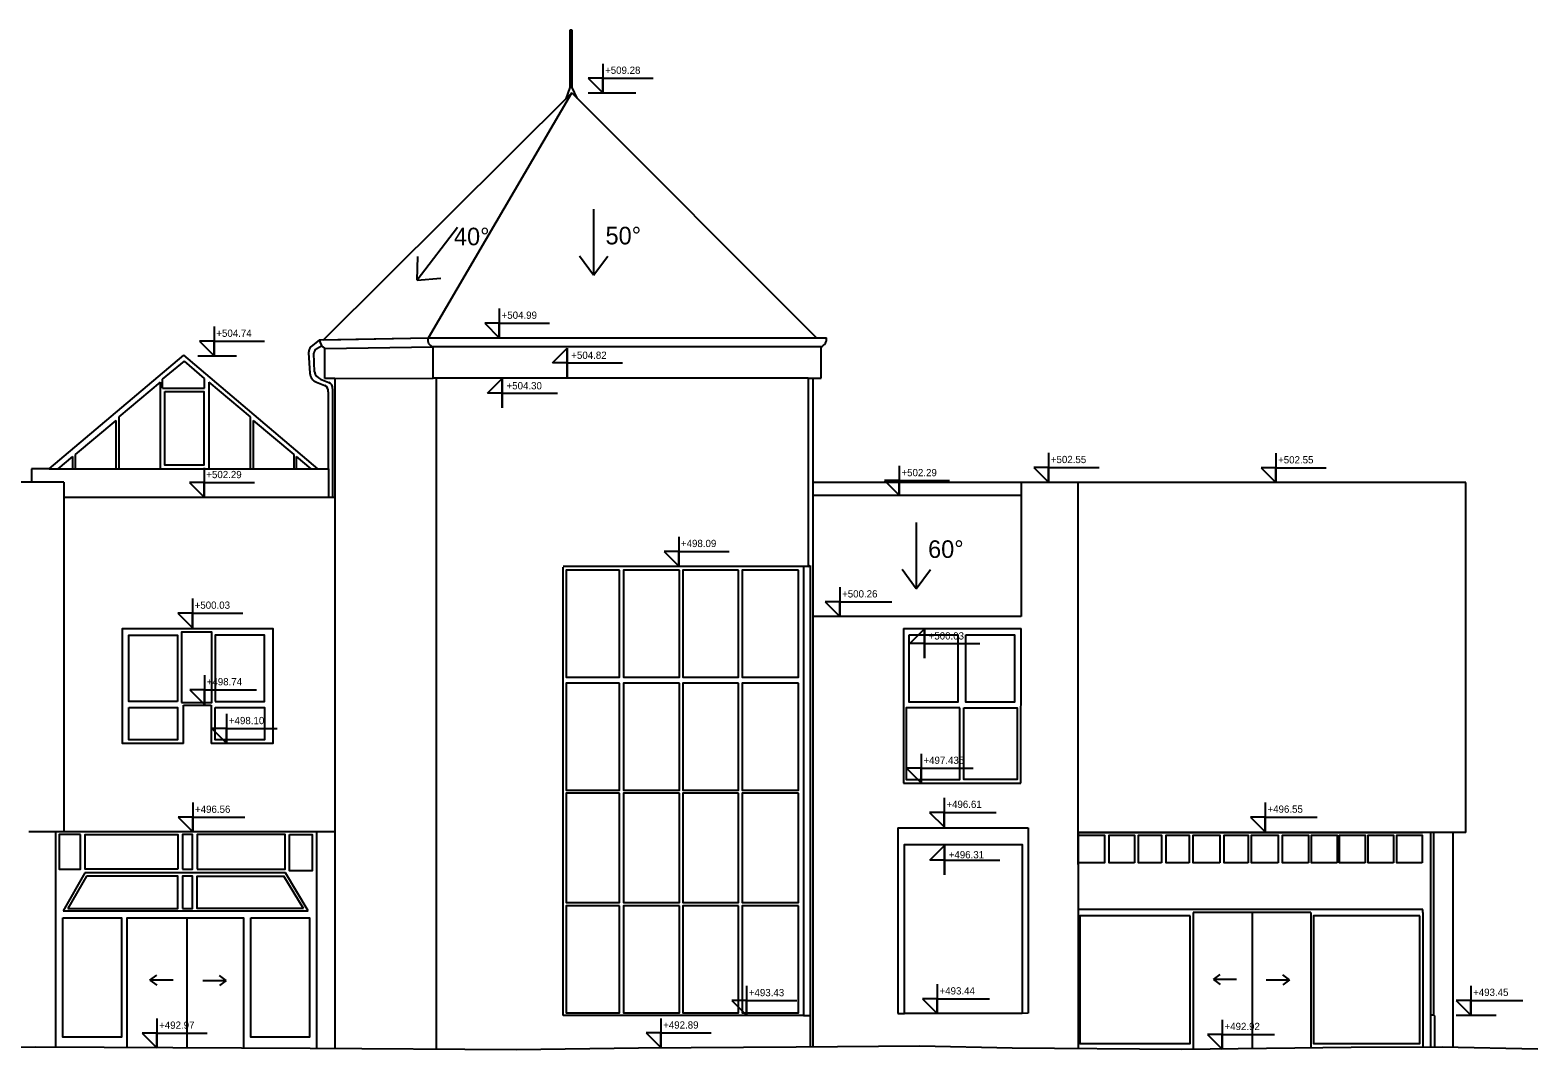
# Model space of a CAD drawing. Extents: x 3.3 to 94, y 492.8 to 514.5.
# Drawn here: x 68.21 to 93.96, y 492.85 to 510.27 of the extents above; entities that cross this region are included whole.
import ezdxf

# ---------------------------------------------------------------- set-up
doc = ezdxf.new("R2010")
doc.units = 0
for name, color, linetype in [('antena', 7, 'Continuous'), ('dvere', 7, 'Continuous'), ('okap', 7, 'Continuous'), ('okna', 7, 'Continuous'), ('strecha_sikma', 7, 'Continuous'), ('svetlik', 7, 'Continuous'), ('teren', 7, 'Continuous'), ('zakl_tenka', 7, 'Continuous'), ('znaceni', 7, 'Continuous')]:
    doc.layers.add(name, color=color, linetype=linetype)

msp = doc.modelspace()

# ---------------------------------------------------------------- linework, layer by layer
at = {"layer": 'antena'}
for p, q in [((77.465, 510.27), (77.425, 510.27)), ((77.425, 510.27), (77.425, 509.29)), ((77.465, 509.29), (77.465, 510.27)), ((77.425, 509.29), (77.355, 509.099)), ((77.55, 509.106), (77.465, 509.29))]:
    msp.add_line(p, q, dxfattribs=at)
at = {"layer": 'dvere'}
for p, q in [((88.07, 495.196), (88.07, 492.859)), ((90.08, 495.196), (88.07, 495.196)), ((89.08, 495.196), (89.08, 492.871)), ((90.08, 495.196), (90.08, 492.882)), ((70.885, 495.109), (70.885, 492.884))]:
    msp.add_line(p, q, dxfattribs=at)
msp.add_lwpolyline([(72.638, 496.531), (73.021, 496.531), (73.021, 495.907), (72.638, 495.907)], close=True, dxfattribs=at)
msp.add_lwpolyline([(69.865, 492.889), (69.865, 495.109), (71.853, 495.109), (71.853, 492.879)], dxfattribs=at)
at = {"layer": 'okap'}
for p, q in [((73.148, 504.977), (73.002, 504.859)), ((73.148, 504.977), (75.009, 505.013)), ((75.009, 505.013), (81.807, 505.012)), ((72.963, 504.759), (72.982, 504.408)), ((73.062, 504.432), (73.053, 504.75)), ((73.101, 504.83), (73.185, 504.876)), ((73.242, 504.834), (75.09, 504.861)), ((81.718, 504.861), (75.09, 504.861)), ((73.096, 504.256), (73.241, 504.199)), ((73.166, 504.31), (73.31, 504.252)), ((73.299, 504.092), (73.299, 502.774)), ((73.369, 504.145), (73.369, 502.293))]:
    msp.add_line(p, q, dxfattribs=at)
for centre, radius, start, end in [((73.335, 504.999), 0.189, 186.7221, 240.5714), ((75.111, 504.97), 0.111, 157.5198, 258.6908), ((81.664, 504.995), 0.144, 291.9434, 6.8704), ((73.12, 504.756), 0.157, 138.9853, 178.7942), ((73.159, 504.741), 0.107, 123.0247, 174.7703), ((73.226, 504.465), 0.167, 191.3772, 249.1497), ((73.171, 504.431), 0.19, 186.8763, 246.9983), ((73.198, 504.106), 0.102, 351.9431, 65.2903), ((73.268, 504.16), 0.102, 351.9431, 65.2903)]:
    msp.add_arc(centre, radius, start, end, dxfattribs=at)
at = {"layer": 'okna'}
for p, q in [((81.413, 501.096), (81.413, 493.438)), ((69.144, 495.874), (68.773, 495.226)), ((69.172, 495.82), (68.853, 495.265)), ((72.569, 495.874), (69.144, 495.874)), ((72.507, 495.874), (72.506, 495.875)), ((72.873, 495.265), (72.539, 495.82)), ((72.958, 495.226), (72.569, 495.874)), ((68.773, 495.226), (72.958, 495.226)), ((91.991, 495.248), (86.103, 495.248))]:
    msp.add_line(p, q, dxfattribs=at)
for points in [[(70.51, 504.1), (71.173, 504.1), (71.173, 502.841), (70.51, 502.841)], [(78.275, 501.045), (77.363, 501.045), (77.363, 499.219), (78.275, 499.219)], [(79.299, 501.045), (78.34, 501.045), (78.34, 499.219), (79.299, 499.219)], [(80.307, 501.045), (79.354, 501.045), (79.354, 499.219), (80.307, 499.219)], [(81.327, 501.045), (80.366, 501.045), (80.366, 499.219), (81.327, 499.219)], [(70.726, 498.805), (69.892, 498.805), (69.892, 499.935), (70.726, 499.935)], [(70.795, 498.787), (71.313, 498.787), (71.313, 499.986), (70.795, 499.986)], [(71.369, 498.805), (72.211, 498.805), (72.211, 499.935), (71.369, 499.935)], [(83.22, 499.939), (84.049, 499.939), (84.049, 498.792), (83.22, 498.792)], [(84.189, 499.939), (85.021, 499.939), (85.021, 498.792), (84.189, 498.792)], [(78.275, 499.115), (77.363, 499.115), (77.363, 497.288), (78.275, 497.288)], [(79.299, 499.115), (78.34, 499.115), (78.34, 497.288), (79.299, 497.288)], [(80.307, 499.115), (79.354, 499.115), (79.354, 497.288), (80.307, 497.288)], [(81.327, 499.115), (80.366, 499.115), (80.366, 497.288), (81.327, 497.288)], [(69.892, 498.7), (70.726, 498.7), (70.726, 498.149), (69.892, 498.149)], [(71.369, 498.7), (72.211, 498.7), (72.211, 498.149), (71.369, 498.149)], [(84.082, 498.696), (83.17, 498.696), (83.17, 497.472), (84.082, 497.472)], [(84.151, 498.696), (85.066, 498.696), (85.066, 497.472), (84.151, 497.472)], [(78.275, 497.234), (77.363, 497.234), (77.363, 495.369), (78.275, 495.369)], [(79.299, 497.234), (78.34, 497.234), (78.34, 495.369), (79.299, 495.369)], [(80.307, 497.234), (79.354, 497.234), (79.354, 495.369), (80.307, 495.369)], [(81.327, 497.234), (80.366, 497.234), (80.366, 495.369), (81.327, 495.369)], [(69.067, 496.531), (68.705, 496.531), (68.705, 495.939), (69.067, 495.939)], [(70.73, 495.939), (69.145, 495.939), (69.145, 496.531), (70.73, 496.531)], [(70.812, 495.941), (70.981, 495.941), (70.981, 496.531), (70.812, 496.531)], [(71.059, 495.941), (72.563, 495.941), (72.563, 496.531), (71.059, 496.531)], [(87.068, 496.044), (86.634, 496.044), (86.634, 496.517), (87.068, 496.517)], [(87.527, 496.044), (87.138, 496.044), (87.138, 496.517), (87.527, 496.517)], [(88.003, 496.044), (87.608, 496.044), (87.608, 496.517), (88.003, 496.517)], [(88.523, 496.044), (88.071, 496.044), (88.071, 496.517), (88.523, 496.517)], [(89.011, 496.044), (88.597, 496.044), (88.597, 496.517), (89.011, 496.517)], [(89.524, 496.044), (89.067, 496.044), (89.067, 496.517), (89.524, 496.517)], [(90.037, 496.044), (89.597, 496.044), (89.597, 496.517), (90.037, 496.517)], [(90.529, 496.044), (90.093, 496.044), (90.093, 496.517), (90.529, 496.517)], [(91.005, 496.044), (90.57, 496.044), (90.57, 496.517), (91.005, 496.517)], [(91.492, 496.044), (91.057, 496.044), (91.057, 496.517), (91.492, 496.517)], [(91.981, 496.044), (91.546, 496.044), (91.546, 496.517), (91.981, 496.517)], [(70.812, 495.265), (70.981, 495.265), (70.981, 495.82), (70.812, 495.82)], [(78.275, 495.31), (77.363, 495.31), (77.363, 493.484), (78.275, 493.484)], [(79.299, 495.31), (78.34, 495.31), (78.34, 493.484), (79.299, 493.484)], [(80.307, 495.31), (79.354, 495.31), (79.354, 493.484), (80.307, 493.484)], [(81.327, 495.31), (80.366, 495.31), (80.366, 493.484), (81.327, 493.484)], [(68.766, 495.109), (69.769, 495.109), (69.769, 493.067), (68.766, 493.067)], [(71.975, 495.109), (72.977, 495.109), (72.977, 493.067), (71.975, 493.067)], [(88.016, 495.144), (86.133, 495.144), (86.133, 492.96), (88.016, 492.96)], [(91.94, 495.144), (90.126, 495.144), (90.126, 492.96), (91.94, 492.96)]]:
    msp.add_lwpolyline(points, close=True, dxfattribs=at)
for points in [[(86.103, 496.517), (86.554, 496.517), (86.554, 496.044), (86.103, 496.044)], [(68.853, 495.265), (70.73, 495.265), (70.73, 495.82), (69.172, 495.82)], [(72.873, 495.265), (71.059, 495.265), (71.059, 495.82), (72.539, 495.82)]]:
    msp.add_lwpolyline(points, dxfattribs=at)
at = {"layer": 'strecha_sikma'}
for p, q in [((77.457, 509.2), (73.218, 504.978)), ((75.009, 505.013), (77.457, 509.2)), ((77.457, 509.2), (81.638, 505.013)), ((73.218, 504.978), (75.009, 505.013)), ((75.009, 505.013), (81.638, 505.013)), ((81.577, 502.324), (85.135, 502.324)), ((85.135, 500.252), (81.577, 500.252))]:
    msp.add_line(p, q, dxfattribs=at)
at = {"layer": 'svetlik'}
for p, q in [((68.53, 502.774), (70.83, 504.719)), ((73.123, 502.774), (70.83, 504.719)), ((70.466, 504.307), (70.843, 504.614)), ((71.184, 504.318), (70.843, 504.614)), ((70.428, 504.257), (69.722, 503.664)), ((70.428, 504.257), (70.428, 502.774)), ((70.465, 504.156), (70.466, 504.307)), ((71.184, 504.156), (71.184, 504.318)), ((71.257, 504.257), (71.257, 502.774)), ((71.257, 504.257), (71.964, 503.664)), ((70.465, 504.156), (71.184, 504.156)), ((69.722, 503.664), (69.722, 502.774)), ((71.964, 503.664), (71.964, 502.774)), ((69.668, 503.6), (68.976, 503.024)), ((69.668, 503.6), (69.668, 502.774)), ((72.018, 503.6), (72.018, 502.774)), ((72.018, 503.6), (72.71, 503.024)), ((68.932, 502.988), (68.683, 502.774)), ((68.932, 502.988), (68.932, 502.774)), ((68.976, 503.024), (68.976, 502.774)), ((72.71, 503.024), (72.71, 502.774)), ((72.753, 502.988), (72.753, 502.774)), ((72.753, 502.988), (73.003, 502.774)), ((73.304, 502.672), (73.304, 502.671))]:
    msp.add_line(p, q, dxfattribs=at)
at = {"layer": 'teren'}
for p, q in [((68.298, 492.896), (66.412, 492.885)), ((72.989, 492.873), (68.298, 492.896)), ((76.513, 492.852), (72.989, 492.873)), ((78.596, 492.879), (76.513, 492.852)), ((81.292, 492.896), (78.596, 492.879)), ((83.399, 492.915), (81.292, 492.896)), ((84.977, 492.882), (83.399, 492.915)), ((87.876, 492.856), (84.977, 492.882)), ((90.769, 492.891), (87.876, 492.856)), ((92.321, 492.9), (90.769, 492.891)), ((93.956, 492.864), (92.321, 492.9))]:
    msp.add_line(p, q, dxfattribs=at)
at = {"layer": 'zakl_tenka'}
for p, q in [((73.242, 504.834), (75.09, 504.861)), ((73.242, 504.319), (73.242, 504.834)), ((75.09, 504.327), (75.09, 504.861)), ((81.718, 504.861), (75.09, 504.861)), ((81.718, 504.327), (81.718, 504.861)), ((73.242, 504.319), (75.09, 504.327)), ((73.409, 504.319), (73.242, 504.319)), ((73.409, 504.319), (73.409, 492.871)), ((81.496, 504.327), (75.09, 504.327)), ((75.143, 504.313), (75.143, 492.86)), ((81.496, 504.327), (81.496, 501.11)), ((81.496, 504.327), (81.718, 504.327)), ((81.577, 504.313), (81.577, 492.899)), ((68.53, 502.774), (68.23, 502.774)), ((68.23, 502.774), (68.23, 502.549)), ((68.53, 502.774), (73.123, 502.774)), ((73.123, 502.774), (73.304, 502.774)), ((73.304, 502.774), (73.304, 502.293)), ((68.78, 502.549), (61.242, 502.549)), ((68.78, 502.549), (68.78, 496.569)), ((85.135, 502.541), (81.577, 502.541)), ((92.724, 502.541), (85.135, 502.541)), ((85.135, 502.541), (85.135, 500.252)), ((86.103, 496.564), (86.103, 502.541)), ((92.724, 496.564), (92.724, 502.541)), ((68.78, 502.293), (73.409, 502.293)), ((81.496, 501.11), (77.311, 501.11)), ((77.313, 493.438), (77.313, 501.096)), ((81.496, 501.11), (81.531, 501.128)), ((81.531, 501.128), (81.531, 492.898)), ((83.121, 500.047), (85.131, 500.047)), ((83.121, 500.047), (83.121, 497.407)), ((85.129, 497.407), (85.131, 500.047)), ((70.828, 498.086), (70.828, 498.741)), ((70.828, 498.741), (71.299, 498.741)), ((71.299, 498.741), (71.299, 498.086)), ((83.121, 497.407), (85.129, 497.407)), ((73.409, 496.574), (68.185, 496.574)), ((68.642, 496.574), (68.642, 492.894)), ((73.098, 496.574), (73.098, 492.873)), ((83.026, 496.647), (85.251, 496.647)), ((83.026, 496.647), (83.026, 493.473)), ((85.251, 496.647), (85.251, 493.481)), ((92.724, 496.564), (86.103, 496.564)), ((86.103, 496.564), (86.103, 492.872)), ((86.103, 496.017), (86.103, 496.564)), ((86.103, 496.564), (91.985, 496.564)), ((92.121, 496.564), (92.121, 492.898)), ((92.173, 496.564), (92.173, 493.447)), ((92.503, 496.564), (92.503, 492.896)), ((86.103, 495.196), (86.103, 492.872)), ((91.991, 495.196), (91.991, 495.248)), ((91.991, 495.196), (91.991, 492.898)), ((81.413, 493.438), (77.313, 493.438)), ((81.413, 493.438), (81.531, 493.438)), ((83.026, 493.473), (83.138, 493.473)), ((85.148, 493.473), (83.138, 493.473)), ((85.251, 493.481), (85.148, 493.473)), ((92.173, 493.447), (92.121, 493.447)), ((92.173, 493.447), (92.189, 493.435)), ((92.189, 493.435), (92.189, 492.899))]:
    msp.add_line(p, q, dxfattribs=at)
for points in [[(70.828, 498.086), (69.783, 498.086), (69.783, 500.051), (72.354, 500.051), (72.354, 498.086), (71.299, 498.086)], [(83.138, 493.473), (83.138, 496.358), (85.148, 496.358), (85.148, 493.473)]]:
    msp.add_lwpolyline(points, dxfattribs=at)
at = {"layer": 'znaceni'}
for p, q in [((77.987, 509.697), (77.987, 509.197)), ((77.987, 509.447), (77.737, 509.447)), ((77.737, 509.447), (77.987, 509.197)), ((77.987, 509.197), (77.987, 509.447)), ((77.987, 509.447), (78.847, 509.447)), ((77.737, 509.197), (78.554, 509.197)), ((77.831, 507.213), (77.831, 506.083)), ((75.505, 506.898), (74.818, 506)), ((74.818, 506), (74.826, 506.406)), ((77.831, 506.083), (77.59, 506.41)), ((77.831, 506.083), (78.072, 506.41)), ((74.818, 506), (75.223, 506.035)), ((76.22, 505.513), (76.22, 505.013)), ((71.348, 505.205), (71.348, 504.705)), ((76.22, 505.263), (75.97, 505.263)), ((75.97, 505.263), (76.22, 505.013)), ((76.22, 505.013), (76.22, 505.263)), ((76.22, 505.263), (77.079, 505.263)), ((71.348, 504.955), (71.098, 504.955)), ((71.098, 504.955), (71.348, 504.705)), ((71.348, 504.705), (71.348, 504.955)), ((71.348, 504.955), (72.21, 504.955)), ((71.069, 504.705), (71.73, 504.705)), ((77.126, 504.589), (77.376, 504.839)), ((77.376, 504.839), (77.376, 504.339)), ((77.376, 504.339), (77.376, 504.839)), ((77.376, 504.839), (77.376, 504.589)), ((77.376, 504.589), (77.126, 504.589)), ((77.376, 504.589), (77.126, 504.589)), ((77.376, 504.339), (77.376, 504.589)), ((77.376, 504.589), (78.322, 504.589)), ((77.376, 504.589), (78.322, 504.589)), ((76.02, 504.067), (76.27, 504.317)), ((76.27, 504.317), (76.27, 503.817)), ((76.27, 503.817), (76.27, 504.317)), ((76.27, 504.317), (76.27, 504.067)), ((76.27, 504.067), (76.02, 504.067)), ((76.27, 504.067), (76.02, 504.067)), ((76.27, 503.817), (76.27, 504.067)), ((76.27, 504.067), (77.215, 504.067)), ((76.27, 504.067), (77.215, 504.067)), ((85.6, 503.049), (85.6, 502.549)), ((89.482, 503.043), (89.482, 502.543)), ((71.177, 502.792), (71.177, 502.292)), ((83.049, 502.825), (83.049, 502.325)), ((85.6, 502.799), (85.35, 502.799)), ((85.35, 502.799), (85.6, 502.549)), ((85.6, 502.549), (85.6, 502.799)), ((85.6, 502.799), (86.462, 502.799)), ((89.482, 502.793), (89.232, 502.793)), ((89.232, 502.793), (89.482, 502.543)), ((89.482, 502.543), (89.482, 502.793)), ((89.482, 502.793), (90.343, 502.793)), ((71.177, 502.542), (70.927, 502.542)), ((70.927, 502.542), (71.177, 502.292)), ((71.177, 502.292), (71.177, 502.542)), ((71.177, 502.542), (72.038, 502.542)), ((83.049, 502.575), (82.799, 502.575)), ((82.799, 502.575), (83.049, 502.325)), ((83.049, 502.325), (83.049, 502.575)), ((83.049, 502.575), (83.91, 502.575)), ((83.34, 501.858), (83.34, 500.728)), ((79.283, 501.614), (79.283, 501.114)), ((79.283, 501.364), (79.033, 501.364)), ((79.033, 501.364), (79.283, 501.114)), ((79.283, 501.114), (79.283, 501.364)), ((79.283, 501.364), (80.145, 501.364)), ((83.34, 500.728), (83.099, 501.055)), ((83.34, 500.728), (83.581, 501.055)), ((70.978, 500.56), (70.978, 500.06)), ((82.036, 500.753), (82.036, 500.253)), ((70.978, 500.31), (70.728, 500.31)), ((70.728, 500.31), (70.978, 500.06)), ((70.978, 500.06), (70.978, 500.31)), ((70.978, 500.31), (71.84, 500.31)), ((82.036, 500.503), (81.786, 500.503)), ((81.786, 500.503), (82.036, 500.253)), ((82.036, 500.253), (82.036, 500.503)), ((82.036, 500.503), (82.925, 500.503)), ((83.229, 499.795), (83.479, 500.045)), ((83.479, 500.045), (83.479, 499.545)), ((83.479, 499.545), (83.479, 500.045)), ((83.479, 500.045), (83.479, 499.795)), ((83.479, 499.795), (83.229, 499.795)), ((83.479, 499.795), (83.229, 499.795)), ((83.479, 499.545), (83.479, 499.795)), ((83.479, 499.795), (84.425, 499.795)), ((83.479, 499.795), (84.425, 499.795)), ((71.184, 499.252), (71.184, 498.752)), ((71.184, 499.002), (70.934, 499.002)), ((70.934, 499.002), (71.184, 498.752)), ((71.184, 498.752), (71.184, 499.002)), ((71.184, 499.002), (72.074, 499.002)), ((71.563, 498.59), (71.563, 498.09)), ((71.563, 498.34), (71.313, 498.34)), ((71.313, 498.34), (71.563, 498.09)), ((71.563, 498.09), (71.563, 498.34)), ((71.563, 498.34), (72.424, 498.34)), ((83.424, 497.911), (83.424, 497.411)), ((83.424, 497.661), (83.174, 497.661)), ((83.174, 497.661), (83.424, 497.411)), ((83.424, 497.411), (83.424, 497.661)), ((83.424, 497.661), (84.313, 497.661)), ((70.984, 497.075), (70.984, 496.575)), ((83.817, 497.159), (83.817, 496.659)), ((89.301, 497.076), (89.301, 496.576)), ((70.984, 496.825), (70.734, 496.825)), ((70.734, 496.825), (70.984, 496.575)), ((70.984, 496.575), (70.984, 496.825)), ((70.984, 496.825), (71.873, 496.825)), ((83.817, 496.909), (83.567, 496.909)), ((83.567, 496.909), (83.817, 496.659)), ((83.817, 496.659), (83.817, 496.909)), ((83.817, 496.909), (84.706, 496.909)), ((89.301, 496.826), (89.051, 496.826)), ((89.051, 496.826), (89.301, 496.576)), ((89.301, 496.576), (89.301, 496.826)), ((89.301, 496.826), (90.19, 496.826)), ((83.572, 496.092), (83.822, 496.342)), ((83.822, 496.342), (83.822, 495.842)), ((83.822, 495.842), (83.822, 496.342)), ((83.822, 496.342), (83.822, 496.092)), ((83.822, 496.092), (83.572, 496.092)), ((83.822, 496.092), (83.572, 496.092)), ((83.822, 495.842), (83.822, 496.092)), ((83.822, 496.092), (84.767, 496.092)), ((83.822, 496.092), (84.767, 496.092)), ((70.254, 494.041), (70.369, 494.125)), ((71.553, 494.036), (71.439, 494.121)), ((88.415, 494.054), (88.53, 494.138)), ((89.714, 494.049), (89.599, 494.134)), ((70.652, 494.041), (70.254, 494.041)), ((70.254, 494.041), (70.369, 493.956)), ((71.156, 494.036), (71.553, 494.036)), ((71.553, 494.036), (71.439, 493.951)), ((80.442, 493.943), (80.442, 493.443)), ((83.699, 493.973), (83.699, 493.473)), ((88.812, 494.054), (88.415, 494.054)), ((88.415, 494.054), (88.53, 493.969)), ((89.317, 494.049), (89.714, 494.049)), ((89.714, 494.049), (89.599, 493.964)), ((92.812, 493.947), (92.812, 493.447)), ((80.442, 493.693), (80.192, 493.693)), ((80.192, 493.693), (80.442, 493.443)), ((80.442, 493.443), (80.442, 493.693)), ((80.442, 493.693), (81.303, 493.693)), ((83.699, 493.723), (83.449, 493.723)), ((83.449, 493.723), (83.699, 493.473)), ((83.699, 493.473), (83.699, 493.723)), ((83.699, 493.723), (84.589, 493.723)), ((92.812, 493.697), (92.562, 493.697)), ((92.562, 493.697), (92.812, 493.447)), ((92.812, 493.447), (92.812, 493.697)), ((92.812, 493.697), (93.701, 493.697)), ((70.372, 493.386), (70.372, 492.886)), ((78.979, 493.39), (78.979, 492.89)), ((88.566, 493.364), (88.566, 492.864)), ((92.562, 493.447), (93.242, 493.447)), ((70.372, 493.136), (70.122, 493.136)), ((70.122, 493.136), (70.372, 492.886)), ((70.372, 492.886), (70.372, 493.136)), ((70.372, 493.136), (71.233, 493.136)), ((78.979, 493.14), (78.729, 493.14)), ((78.729, 493.14), (78.979, 492.89)), ((78.979, 492.89), (78.979, 493.14)), ((78.979, 493.14), (79.84, 493.14)), ((88.566, 493.114), (88.316, 493.114)), ((88.316, 493.114), (88.566, 492.864)), ((88.566, 492.864), (88.566, 493.114)), ((88.566, 493.114), (89.456, 493.114))]:
    msp.add_line(p, q, dxfattribs=at)

# ---------------------------------------------------------------- texts
for s, height, p in [('+509.28', 0.124, (78.026, 509.523)), ('40°', 0.3, (75.446, 506.595)), ('50°', 0.3, (78.034, 506.61)), ('+504.99', 0.124, (76.259, 505.339)), ('+504.74', 0.124, (71.387, 505.031)), ('+504.82', 0.124, (77.449, 504.655)), ('+504.30', 0.124, (76.343, 504.134)), ('+502.55', 0.124, (85.639, 502.874)), ('+502.55', 0.124, (89.52, 502.869)), ('+502.29', 0.124, (71.216, 502.617)), ('+502.29', 0.124, (83.088, 502.65)), ('+498.09', 0.124, (79.322, 501.44)), ('60°', 0.3, (83.543, 501.255)), ('+500.26', 0.124, (82.074, 500.579)), ('+500.03', 0.124, (71.017, 500.386)), ('+500.03', 0.124, (83.552, 499.861)), ('+498.74', 0.124, (71.223, 499.078)), ('+498.10', 0.124, (71.602, 498.415)), ('+497.435', 0.124, (83.463, 497.736)), ('+496.56', 0.124, (71.023, 496.9)), ('+496.61', 0.124, (83.855, 496.984)), ('+496.55', 0.124, (89.339, 496.902)), ('+496.31', 0.124, (83.895, 496.123)), ('+493.43', 0.124, (80.481, 493.768)), ('+493.44', 0.124, (83.738, 493.798)), ('+493.45', 0.124, (92.85, 493.773)), ('+492.97', 0.124, (70.41, 493.212)), ('+492.89', 0.124, (79.018, 493.215)), ('+492.92', 0.124, (88.605, 493.19))]:
    msp.add_text(s, height=height, dxfattribs=at).set_placement(p)

doc.saveas('drawing.dxf')
